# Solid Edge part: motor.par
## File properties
Author: Argu
Template: iso part.par
Last saved by: argo
Revision: 174
Application: Solid Edge
Accuracy: 0,990
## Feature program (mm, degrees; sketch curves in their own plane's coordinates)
lofted protrusion "unnamed LoftedProtrusion 1"
sketch for "unnamed RevolvedProtrusion 1" plane through (0, 0, 0) normal (0.994522, 0, 0.104528) x-axis (0, 1, 0)
  line (24, -36.69) -> (24, -42.69)
revolve "unnamed RevolvedProtrusion 1" add full turn 360 deg
sketch for "väljalase" plane through (0, 213, 0) normal (0, 1, 0) x-axis (-1, 0, 0)
  line (10.5863, -6.6244) -> (4.6567, -16.1368)
  line (-11.713, -4.3174) -> (-7.8564, -14.8423)
extrude "väljalase" add finite 25 along +normal
sketch for "unnamed Protrusion 1" plane through (0, 213, 0) normal (0, 1, 0) x-axis (-1, 0, 0)
  line (10.5863, -6.6244) -> (4.6567, -16.1368)
  line (-11.713, -4.3174) -> (-7.8564, -14.8423)
extrude "unnamed Protrusion 1" add finite 25 along -normal
replace surface "unnamed ReplaceSurface 1"
lofted protrusion "unnamed LoftedProtrusion 2"
sketch for "küljeosapea" plane through (19.2941, 50, 0) normal (0, -1, 0) x-axis (0, 0, -1)
  line (-13.3856, 0.4611) -> (13.3856, 0.4611)
revolve "küljeosapea" add finite 90 deg
sketch for "küljeõhukogur" plane through (22.9602, 97.2349, -43.0717) normal (-0.99115, -0.132749, 2e-06) x-axis (2e-06, 0, 1)
  line (38.5171, 57.7287) -> (15.9515, 59.6618)
  line (15.9515, 59.6618) -> (17.6852, 79.8989)
  line (17.6852, 79.8989) -> (40.2507, 77.9658)
  line (40.2507, 77.9658) -> (38.5171, 57.7287)
extrude "küljeõhukogur" add finite 10 along -normal
sketch for "tiivaühendust90kraadi" plane through (0, 0, 0) normal (1, 0, 0) x-axis (0, 1, 0)
  arc centre (60, 1124.0766) radius 1136.5766 from (60, -12.5) to (165.0001, -7.6395) ccw
  arc centre (60, -384.4611) radius 396.9611 from (60, 12.5) to (165.0006, -1.6387) cw
extrude "tiivaühendust90kraadi" add finite 35 along -normal
lofted protrusion "unnamed LoftedProtrusion 3"
sketch used by "unnamed Cutout 1" plane through (0, 0, 0) normal (0, -1, 0) x-axis (1, 0, 0)
extrude "unnamed Cutout 1" cut finite 25 along -normal
draft "unnamed Draft 1"
sketch used by "küljekogur_tühjaks" plane through (19.4676, 155.9842, -15.8113) normal (0.132264, -0.987533, -0.085355) x-axis (0.99115, 0.132749, -2e-06)
extrude "küljekogur_tühjaks" cut finite 18 along -normal
fillet "unnamed Round 1"
fillet "küljekogurinurgad2" radius 0.5
fillet "küljekogurinurgad3" radius 1
fillet "küljekogurinurgad4" radius 0.5
fillet "küljekogurinurgad5" radius 0.5
web network "väljalaskeava_ribid"  Thickness = 0.25 mm
sketch for "tiivatugi" plane through (0, -24, 0) normal (0, -1, 0) x-axis (1, 0, 0)
  line (-280.7164, 2.3908) -> (-280.5824, 2.3963)
  line (-280.5824, 2.3963) -> (-275.909, -42.0686)
  line (-284.9125, -72.0686) -> (-275.909, -42.0686)
  line (-340.5, -72.0686) -> (-284.9125, -72.0686)
  line (-340.5, -0.0686) -> (-340.5, -72.0686)
  line (-340.5, -0.0686) -> (-340.5, 2.3908)
  line (-280.7164, 2.3908) -> (-340.5, 2.3908)
extrude "tiivatugi" add finite 300 along -normal
fillet "Round_13" radius 25
sketch for "unnamed Cutout 2" plane through (-280.5, 0, 0) normal (1, 0, 0) x-axis (0, 1, 0)
  arc centre (78.2888, -220.2096) radius 222.6118 from (-24, -22.4901) to (79.9131, 2.3963) cw
  line (177.7767, -5.9179) -> (276, -22.4901)
extrude "unnamed Cutout 2" cut to key point along -normal
sketch for "unnamed Cutout 3" plane through (-280.5, 0, 0) normal (1, 0, 0) x-axis (0, 1, 0)
  line (177.7767, -5.9179) -> (276, -22.4901)
extrude "unnamed Cutout 3" cut to key point along +normal
fillet "unnamed Round 2"
sketch for "tiivatugi_tühjaks" plane through (0, -49, 0) normal (0, -1, 0) x-axis (1, 0, 0)
  line (-308.2912, -146.1981) -> (-294.1065, -138.9677)
  line (-294.1065, -138.9677) -> (-293.6547, -137.845)
  arc centre (-385.4277, -100.9117) radius 98.926 from (-293.6547, -137.845) to (-286.5972, -105.2589) ccw
  line (-286.5972, -105.2589) -> (-285.1373, -72.0686)
  line (-285.1373, -72.0686) -> (-289.4197, -42.5492)
  arc centre (-299.6692, -44.0361) radius 10.3568 from (-289.4197, -42.5492) to (-294.2246, -35.2258) ccw
  line (-294.2246, -35.2258) -> (-295.5114, -34.4306)
  arc centre (-311.2831, -59.9517) radius 30.0011 from (-295.5114, -34.4306) to (-309.524, -30.0022) ccw
  line (-309.524, -30.0022) -> (-340.5, -28.1828)
  line (-340.5, -28.1828) -> (-340.5, -148.1828)
  line (-340.5, -148.1828) -> (-308.2912, -146.1981)
extrude "tiivatugi_tühjaks" cut finite 525 along -normal
sketch for "unnamed Protrusion 2" plane through (-310.8984, -24, -43.202) normal (0, -1, 0) x-axis (1, 0, 0)
  line (2.6071, -102.9961) -> (16.7918, -95.7657)
  line (-29.6016, -104.9808) -> (2.6071, -102.9961)
  line (-29.6016, 15.0192) -> (-29.6016, -104.9808)
  line (1.3744, 13.1999) -> (-29.6016, 15.0192)
  arc centre (-0.3847, -16.7496) radius 30.0011 from (15.3869, 8.7714) to (1.3744, 13.1999) ccw
  line (16.6737, 7.9762) -> (15.3869, 8.7714)
  arc centre (11.2291, -0.834) radius 10.3568 from (21.4787, 0.6529) to (16.6737, 7.9762) ccw
  line (25.7611, -28.8666) -> (21.4787, 0.6529)
  line (24.3011, -62.0569) -> (25.7611, -28.8666)
  arc centre (-74.5293, -57.7096) radius 98.926 from (17.2436, -94.643) to (24.3011, -62.0569) ccw
extrude "unnamed Protrusion 2" add to key point along -normal
sketch for "kereninaosa" plane through (-310.8984, -24, -43.202) normal (0, -1, 0) x-axis (1, 0, 0)
  line (2.6071, -102.9961) -> (16.7918, -95.7657)
  line (-29.6016, -104.9808) -> (2.6071, -102.9961)
  line (-29.6016, 15.0192) -> (-29.6016, -104.9808)
  line (1.3744, 13.1999) -> (-29.6016, 15.0192)
  arc centre (-0.3847, -16.7496) radius 30.0011 from (15.3869, 8.7714) to (1.3744, 13.1999) ccw
  line (16.6737, 7.9762) -> (15.3869, 8.7714)
  arc centre (11.2291, -0.834) radius 10.3568 from (21.4787, 0.6529) to (16.6737, 7.9762) ccw
  line (25.7611, -28.8666) -> (21.4787, 0.6529)
  line (24.3011, -62.0569) -> (25.7611, -28.8666)
  arc centre (-74.5293, -57.7096) radius 98.926 from (17.2436, -94.643) to (24.3011, -62.0569) ccw
extrude "kereninaosa" add finite 192 along +normal
lofted protrusion "unnamed LoftedProtrusion 4"
swept protrusion "SweptProtrusion_23"
replace surface "unnamed ReplaceSurface 2"
sketch for "unnamed Cutout 4" plane through (-338.3961, 165.0002, -75) normal (0, 0, 1) x-axis (0, 1, 0)
  arc centre (-334.7471, 13.2391) radius 47.5746 from (-355.6953, -29.4753) to (-381.0002, 2.1039) cw
  line (-340.8749, -38.1444) -> (-355.6953, -29.4753)
  arc centre (-312.4363, 10.4733) radius 56.3243 from (-318.7086, -45.5007) to (-340.8749, -38.1444) cw
  line (-262.505, -51.7988) -> (-318.7086, -45.5007)
  line (-262.505, -51.7988) -> (-223.4421, -53.2588)
extrude "unnamed Cutout 4" cut finite 250 along -normal
sketch for "unnamed Cutout 5" plane through (-338.3961, 165.0002, -75) normal (0, 0, 1) x-axis (0, 1, 0)
  arc centre (-334.7471, 13.2391) radius 47.5746 from (-355.6953, -29.4753) to (-381.0002, 2.1039) cw
  line (-340.8749, -38.1444) -> (-355.6953, -29.4753)
  arc centre (-312.4363, 10.4733) radius 56.3243 from (-318.7086, -45.5007) to (-340.8749, -38.1444) cw
  line (-262.505, -51.7988) -> (-318.7086, -45.5007)
  line (-262.505, -51.7988) -> (-223.4421, -53.2588)
extrude "unnamed Cutout 5" cut to key point along +normal
sketch for "tagatiib" plane through (-340.5, 165.0002, -72.8961) normal (-1, 0, 0) x-axis (0, -1, 0)
  line (-446.2782, 53.6797) -> (-327.0292, 50.3776)
  line (-358.6945, 20.6286) -> (-327.4416, 25.629)
  line (-446.9998, 27.6211) -> (-358.6945, 20.6286)
extrude "tagatiib" add finite 120 along -normal
lofted protrusion "unnamed LoftedProtrusion 5"
lofted protrusion "unnamed LoftedProtrusion 6"
sketch for "unnamed RevolvedProtrusion 2" plane through (-225.6219, 579.9977, 99.9635) normal (0, -0.02768, 0.999617) x-axis (0, 0.999617, 0.02768)
revolve "unnamed RevolvedProtrusion 2" add finite 360 deg
sketch for "unnamed RevolvedProtrusion 3" plane through (-225.6219, 578.047, -80.1595) normal (0, 0.02768, -0.999617) x-axis (1, 0, 0)
  line (0, 44.8751) -> (0, -44.8781)
  arc centre (0, -42.3781) radius 2.5 from (0, -44.8781) to (2.5, -42.3781) ccw
  line (2.5, 42.3751) -> (2.5, -42.3781)
  arc centre (0, 42.3751) radius 2.5 from (2.5, 42.3751) to (0, 44.8751) ccw
revolve "unnamed RevolvedProtrusion 3" add finite 360 deg
body pattern "unnamed BodyPattern 1"
pattern "unnamed Pattern 1"
fillet "Round_41" radius 25
sketch for "kerelaiend" plane through (-340.5, 194.9376, -97.143) normal (-1, 0, 0) x-axis (0, -0.999989, 0.00463)
  line (-161.3545, -6.1088) -> (-30.218, -41.6853)
  line (-30.218, -41.6853) -> (-10.9684, 29.2697)
  line (-5.2997, 50.2919) -> (-10.9684, 29.2697)
  line (-141.7314, 50.9586) -> (-5.2997, 50.2919)
  arc centre (-141.8871, 19.1047) radius 31.8543 from (-141.7314, 50.9586) to (-161.3545, -6.1088) ccw
revolve "kerelaiend" add finite 180 deg
sketch for "kerelaiend2" plane through (0, 224.9622, 0) normal (0, -1, 0) x-axis (1, 0, 0)
  line (-476.3766, -138.9677) -> (-386.8935, -138.9677)
  line (-294.1065, -138.9677) -> (-386.8935, -138.9677)
  line (-204.6234, -138.9677) -> (-294.1065, -138.9677)
  line (-281.8752, -61.9482) -> (-208.6199, -80.7816)
  line (-281.8752, -61.9482) -> (-399.1248, -61.9482)
  line (-399.1248, -61.9482) -> (-472.3801, -80.7816)
extrude "kerelaiend2" add finite 150 along +normal
sketch for "kerelaiend3" plane through (-441.4689, 74.9622, -100.458) normal (0, -1, 0) x-axis (1, 0, 0)
  line (-34.9077, -38.5098) -> (54.5754, -38.5098)
  line (100.9689, -38.5098) -> (54.5754, -38.5098)
  line (100.9689, 38.5098) -> (100.9689, -38.5098)
  line (100.9689, 38.5098) -> (42.3441, 38.5098)
  line (42.3441, 38.5098) -> (-30.9112, 19.6764)
revolve "kerelaiend3" add finite 180 deg
sketch for "rattaava" plane through (-249.3649, 86.1067, -138.9677) normal (0, 0, -1) x-axis (1, 0, 0)
  line (-77.1351, 242.1067) -> (-77.1351, 187.1067)
  line (-77.1351, 187.1067) -> (-108.6108, 187.1067)
  line (-108.6108, 187.1067) -> (-108.6108, 242.1067)
  line (-108.6108, 242.1067) -> (-91.1351, 242.1067)
  line (-91.1351, 242.1067) -> (-77.1351, 242.1067)
extrude "rattaava" cut finite 25 along +normal
sketch for "rattaava2" plane through (-249.3649, 86.1067, -138.9677) normal (0, 0, -1) x-axis (1, 0, 0)
  line (-91.1351, 242.1067) -> (-77.1351, 242.1067)
  line (-77.1351, 242.1067) -> (-77.1351, 187.1067)
  line (-77.1351, 187.1067) -> (-108.6108, 187.1067)
  line (-108.6108, 187.1067) -> (-108.6108, 242.1067)
  line (-108.6108, 242.1067) -> (-91.1351, 242.1067)
extrude "rattaava2" cut finite 5 along -normal
sketch for "tagarattaava" plane through (-249.3649, 86.1067, -138.9677) normal (0, 0, -1) x-axis (1, 0, 0)
  line (12.8649, -36.3933) -> (-18.5846, -36.3933)
  line (-18.5846, -36.3933) -> (-18.5846, -91.3933)
  line (-18.5846, -91.3933) -> (-1.1351, -91.3933)
  line (-1.1351, -91.3933) -> (12.8649, -91.3933)
  line (12.8649, -91.3933) -> (12.8649, -36.3933)
extrude "tagarattaava" cut finite 5 along -normal
mirror "unnamed Mirror 1" of "tagarattaava" about plane through (-340.5, 194.9376, -97.143) normal (-1, 0, 0)
extrude "unnamed Cutout 6" cut finite 5
fillet "unnamed Round 3"
sketch for "kabiiniaken" plane through (-340.5, -157.7277, -58.887) normal (0, -0.783072, 0.621931) x-axis (1, 0, 0)
  arc centre (30.5182, 14.9052) radius 10 from (40.4763, 13.9912) to (34.5082, 24.0747) ccw
  arc centre (0, -55.2287) radius 86.4861 from (34.5082, 24.0747) to (-34.5082, 24.0747) ccw
  arc centre (-30.5182, 14.9052) radius 10 from (-34.5082, 24.0747) to (-40.4763, 13.9912) ccw
  line (-40.4763, 13.9912) -> (-37.917, -13.8913)
  arc centre (-32.9379, -13.4343) radius 5 from (-32.9379, -18.4343) to (-37.917, -13.8913) cw
  line (32.9379, -18.4343) -> (-32.9379, -18.4343)
  arc centre (32.9379, -13.4343) radius 5 from (32.9379, -18.4343) to (37.917, -13.8913) ccw
  line (37.917, -13.8913) -> (40.4763, 13.9912)
extrude "kabiiniaken" cut finite 100 along -normal
sketch for "unnamed Cutout 7" plane through (0, -138.2878, 0) normal (0, -1, 0) x-axis (1, 0, 0)
  line (-380.9763, -47.9309) -> (-378.417, -69.7649)
  line (-378.417, -69.7649) -> (-372.0792, -117.1998)
  line (-308.9208, -116.8926) -> (-372.0792, -117.1998)
  line (-302.583, -69.7649) -> (-308.9208, -116.8926)
  line (-302.583, -69.7649) -> (-300.0237, -47.9309)
extrude "unnamed Cutout 7" cut to key point along -normal
thinwall "Thinwall_22"  Thickness = 0.01 mm
cool vent "õhuaugud"  RibDepth = 2 mm; SparThickness = 2 mm; SparDepth = 2 mm
sketch for "tankimistoru" plane through (0, 0, 0) normal (0, -1, 0) x-axis (1, 0, 0)
  circle centre (-373.4379, -131.7498) radius 7.5
extrude "tankimistoru" add finite 225 along +normal
lofted protrusion "unnamed LoftedProtrusion 7"
fillet "unnamed Round 4"
sketch for "unnamed Protrusion 3" plane through (-272.2835, -18.9938, -29.5985) normal (-0.956613, -0.001235, -0.291359) x-axis (0.00068, 0.999979, -0.006472)
  circle centre (35.1937, 14.8267) radius 17.5
extrude "unnamed Protrusion 3" add to key point along +normal
sketch for "unnamed Protrusion 4" plane through (-272.2835, -18.9938, -29.5985) normal (-0.956613, -0.001235, -0.291359) x-axis (0.00068, 0.999979, -0.006472)
  circle centre (79.539, 14.5434) radius 17.5
extrude "unnamed Protrusion 4" add to key point along +normal
sketch for "unnamed Cutout 8" #1 plane through (-277.0665, -19, -31.0553) normal (-0.956613, -0.001235, -0.291359) x-axis (0.00068, 0.999979, -0.006472)
  circle centre (80.122, 14.5396) radius 14.5443
sketch for "unnamed Cutout 8" #2 plane through (-277.0665, -19, -31.0553) normal (-0.956613, -0.001235, -0.291359) x-axis (0.00068, 0.999979, -0.006472)
  circle centre (35.1937, 14.8267) radius 14.5443
extrude "unnamed Cutout 8" cut to key point symmetric
sketch for "ExtrudedCutout_50" #1 plane through (-413.0604, 16.1044, -44.0095) normal (-0.956613, 0.001235, 0.291359) x-axis (0, -0.999991, 0.004239)
sketch for "ExtrudedCutout_50" #2 plane through (-413.0604, 16.1044, -44.0095) normal (-0.956613, 0.001235, 0.291359) x-axis (0, -0.999991, 0.004239)
  circle centre (0, 0) radius 12.5
extrude "ExtrudedCutout_50" cut finite 100 symmetric
swept protrusion "v_5"
swept protrusion "SweptProtrusion_31"
sketch for "ExtrudedCutout_53" plane through (0, -172.7051, 0) normal (0, -1, 0) x-axis (1, 0, 0)
  circle centre (-324.4536, -98.0234) radius 1.5
extrude "ExtrudedCutout_53" cut finite 50 along -normal
sketch used by "unnamed Protrusion 5" plane through (0, 0, -124.2498) normal (0, 0, 1) x-axis (1, 0, 0)
  circle centre (-326.49, -90.8853) radius 15.8853
extrude "unnamed Protrusion 5" add to key point along -normal
sketch for "unnamed Protrusion 6" plane through (0, 0, -124.2498) normal (0, 0, 1) x-axis (1, 0, 0)
extrude "unnamed Protrusion 6" add to key point along +normal
mirror "unnamed Mirror 2" of "unnamed Protrusion 6" about plane through (-340.5, 194.9376, -97.143) normal (-1, 0, 0)
extrude "unnamed Protrusion 7" add finite 7.1937
sketch for "unnamed Protrusion 8" plane through (-340.4999, -156.6378, -57.5146) normal (0, 0.783072, -0.621931) x-axis (1, -2e-06, -2e-06)
extrude "unnamed Protrusion 8" add finite 5 symmetric
mirror "unnamed Mirror 3" of "unnamed Protrusion 8" about plane through (-340.5, 194.9376, -97.143) normal (-1, 0, 0)
extrude "unnamed Protrusion 9" add finite 5 symmetric
thicken "Thicken_12"  Distance1 = 10 mm
thicken "Thicken_14"  Distance1 = 3.175 mm
thicken "Thicken_15"  Distance1 = 3.175 mm
thicken "Thicken_16"  Distance1 = 3.175 mm
sketch for "ExtrudedProtrusion_60" plane through (-340.5, -157.7277, -58.887) normal (0, -0.783072, 0.621931) x-axis (1, 0, 0)
extrude "ExtrudedProtrusion_60" add finite 1 symmetric
mirror "unnamed Mirror 4" of "unnamed Protrusion 3", "unnamed Protrusion 4" about plane through (-340.5, 194.9376, -97.143) normal (-1, 0, 0)
extrude "unnamed Protrusion 10" add finite 7.5912
extrude "unnamed Protrusion 11" add finite 9.8234
mirror "unnamed Mirror 5" of "unnamed Cutout 8" about plane through (-340.5, 194.9376, -97.143) normal (-1, 0, 0)
extrude "unnamed Cutout 9" cut finite 71.1226 symmetric
sketch for "unnamed Protrusion 12" #1 plane through (-267.9396, 16.1044, -44.0095) normal (0.956613, 0.001235, 0.291359) x-axis (0.291359, 0, -0.956614)
  circle centre (0, 0) radius 14.5443
sketch for "unnamed Protrusion 12" #2 plane through (-267.9396, 16.1044, -44.0095) normal (0.956613, 0.001235, 0.291359) x-axis (0.291359, 0, -0.956614)
  circle centre (0, 44.9293) radius 14.5443
extrude "unnamed Protrusion 12" add finite 5 along -normal
sketch for "ExtrudedCutout_57" #1 plane through (-267.9396, 16.1044, -44.0095) normal (0.956613, 0.001235, 0.291359) x-axis (0.291359, 0, -0.956614)
  circle centre (0, 0) radius 14.5443
sketch for "ExtrudedCutout_57" #2 plane through (-267.9396, 16.1044, -44.0095) normal (0.956613, 0.001235, 0.291359) x-axis (0.291359, 0, -0.956614)
extrude "ExtrudedCutout_57" cut finite 4 along -normal
sketch for "unnamed Protrusion 13" #1 plane through (-413.008, 60.4506, -44.0254) normal (-0.956613, 0.001235, 0.291359) x-axis (0, -0.999991, 0.004239)
  circle centre (-0.5831, 0.0024) radius 14.5443
sketch for "unnamed Protrusion 13" #2 plane through (-413.008, 60.4506, -44.0254) normal (-0.956613, 0.001235, 0.291359) x-axis (0, -0.999991, 0.004239)
  circle centre (44.3458, -0.1798) radius 14.5443
extrude "unnamed Protrusion 13" add to key point along -normal
sketch for "unnamed Cutout 10" #1 plane through (-413.008, 60.4506, -44.0254) normal (-0.956613, 0.001235, 0.291359) x-axis (0, -0.999991, 0.004239)
  circle centre (-0.5831, 0.0024) radius 14.5443
sketch for "unnamed Cutout 10" #2 plane through (-413.008, 60.4506, -44.0254) normal (-0.956613, 0.001235, 0.291359) x-axis (0, -0.999991, 0.004239)
  circle centre (44.3458, -0.1798) radius 14.5443
extrude "unnamed Cutout 10" cut finite 4 along -normal
Other named dimensions: "ExtrudedSurface_3": FiniteDepth = 50 mm | "ExtrudedSurface_14": FiniteDepth = 150 mm | "ExtrudedSurface_20": FiniteDepth = 275 mm
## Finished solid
Body 1: solid body, 4 faces, 10 edges, 8 vertices.
  Faces by surface: plane 2, spline 2
  Edges by curve: line 6, circle 2, spline 2
Body 2: solid body, 4 faces, 10 edges, 8 vertices.
  Faces by surface: plane 2, spline 2
  Edges by curve: line 6, circle 2, spline 2
Body 3: sheet body, 1 face, 1 edge, 0 vertices.
  Faces by surface: plane 1
  Edges by curve: circle 1
Body 4: sheet body, 1 face, 1 edge, 0 vertices.
  Faces by surface: plane 1
  Edges by curve: circle 1
Body 5: sheet body, 1 face, 12 edges, 12 vertices.
  Faces by surface: plane 1
  Edges by curve: circle 5, line 5, spline 2
Body 6: sheet body, 1 face, 4 edges, 4 vertices.
  Faces by surface: plane 1
  Edges by curve: line 4
Body 7: sheet body, 1 face, 8 edges, 8 vertices.
  Faces by surface: spline 1
  Edges by curve: intersection 4, circle 2, spline 2
Body 8: solid body, 3 faces, 2 edges, 0 vertices.
  Faces by surface: plane 2, spline 1
  Edges by curve: circle 2
Body 9: sheet body, 5 faces, 16 edges, 12 vertices.
  Faces by surface: plane 3, cylinder 2
  Edges by curve: line 12, circle 4
Body 10: sheet body, 15 faces, 46 edges, 32 vertices.
  Faces by surface: plane 8, cylinder 7
  Edges by curve: line 32, circle 14
Body 11: sheet body, 1 face, 4 edges, 4 vertices.
  Faces by surface: cylinder 1
  Edges by curve: circle 2, line 2
Body 12: solid body, 3 faces, 2 edges, 0 vertices.
  Faces by surface: plane 2, spline 1
  Edges by curve: circle 2
Body 13: sheet body, 1 face, 8 edges, 8 vertices.
  Faces by surface: spline 1
  Edges by curve: intersection 4, circle 2, spline 2
Body 14: sheet body, 1 face, 4 edges, 4 vertices.
  Faces by surface: spline 1
  Edges by curve: circle 2, spline 2
Body 15: solid body, 1466 faces, 4095 edges, 2656 vertices, 10 internal voids.
  Faces by surface: plane 700, cylinder 388, spline 134, offset 117, torus 49, sphere 28, blend 20, cone 17, swept 11, spun 2
  Edges by curve: line 1791, intersection 1063, circle 683, curve on surface 264, ellipse 215, spline 79
Bounding box of the edges (mm; curved faces can reach further): 746.375 x 910.039 x 348.642, from (-713.6876, -285, -246.1983) to (32.6876, 625.0393, 102.4439).
Cylindrical faces by radius (mm): R0.49 x14, R0.5 x20, R0.51 x6, R1 x4, R1.01 x4, R1.49 x2, R1.5 x3, R1.99 x10, R2 x10, R2.49 x2, R2.5 x2, R2.9904 x2, R3.0004 x2, R3.9281 x8, R3.9381 x8, R4.1681 x8, R4.1781 x8, R4.99 x3, R5 x9, R5.01 x4, R6.932 x8, R6.942 x8, R6.99 x5, R7 x5, R7.172 x8, R7.182 x8, R7.1982 x1, R7.2082 x2, R7.5 x3, R8.3568 x5, R9.4747 x8, R9.4847 x8, R9.7147 x2, R9.7247 x2, R10 x8, R10.01 x4, R10.3468 x2, R10.3568 x2, R11.8334 x12, R12.3677 x2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
Conical faces (half-angle, radius in mm at the cone's reference point): 2.6612 deg R5.2789 x4, 2.6612 deg R5.2888 x4, 3.7063 deg R3.6133 x1, 75.1013 deg R0.0308 x2, 75.1013 deg R0.0334 x2, 75.5819 deg R58.6223 x2, 75.5819 deg R58.6248 x2
Toroidal faces (ring radius, tube radius in mm): R-0.4611 r13.3835 x2, R-0.4611 r13.3935 x2, R0.5 r0.5 x4, R0.5 r0.51 x4, R1.5 r0.49 x8, R1.5 r0.5 x8, R1.7387 r2 x1, R14.5071 r2.99 x6, R14.5071 r3 x6, R20 r4.99 x2, R20 r5 x2, R123.69 r31.8443 x2, R123.69 r31.8543 x2
Spherical faces by radius (mm): R1.49 x4, R1.5 x4, R1.99 x4, R2 x4, R2.49 x4, R2.5 x4, R4.99 x2, R5 x2
Planar faces by outward normal: +x 15, +y 100, +z 10, -x 15, -y 97, -z 14, oblique 457
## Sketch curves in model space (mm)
circle centre (-413.0604, 16.1044, -44.0095) radius 14.5443
circle centre (-413.0073, 61.0336, -44.0256) radius 14.5443
circle centre (-267.9927, 61.0336, -44.0256) radius 14.5443
circle centre (-267.9396, 16.1044, -44.0095) radius 14.5443
circle centre (-324.4536, -172.7051, -98.0234) radius 1.5
circle centre (-326.49, -90.8853, -124.2498) radius 15.8853
circle centre (-354.2265, 263.942, -20.4557) radius 1.45
circle centre (-326.7724, 263.942, -20.4557) radius 1.4495
circle centre (-413.008, 60.4506, -44.0254) radius 12.5
circle centre (-413.0604, 16.1044, -44.0095) radius 12.5
circle centre (-340.4995, 243.1605, -16.9494) radius 25.1515
line (-340.4994, 263.942, -20.4557) -> (-340.4995, 220.3143, -13.0948)
line (-371.1216, 244.4877, -17.1733) -> (-307.7088, 244.4877, -17.1733)
arc centre (-340.5, 239.3803, -33.0617) radius 27.6078 from (-340.5, 263.942, -20.4557) through (-340.5, 243.1552, -5.7132) to (-340.5, 220.3143, -13.0948)
circle centre (-267.992, 60.4506, -44.0254) radius 17.5
circle centre (-267.9396, 16.1044, -44.0095) radius 17.5
circle centre (-272.7758, 61.0274, -45.4824) radius 14.5443
circle centre (-272.7227, 16.0982, -45.4663) radius 14.5443
circle centre (-373.4379, -285, -131.7498) radius 3.6133
circle centre (-373.4379, 0, -131.7498) radius 7.5
line (-286.1296, -83.9663, -65.2284) -> (-289.3445, -83.9663, -43.0672)
line (-288.8681, -78.9663, -46.3511) -> (-286.606, -78.9663, -61.9446)
line (-285.9348, -93.5164, -66.5712) -> (-289.5393, -93.5164, -41.7245)
line (-289.4584, -88.5164, -42.2824) -> (-286.0158, -88.5164, -66.0132)
line (-285.8452, -103.1116, -67.1886) -> (-289.6289, -103.1116, -41.107)
line (-289.6137, -98.1116, -41.2117) -> (-285.8604, -98.1116, -67.084)
line (-286.0487, -107.3914, -65.786) -> (-289.4254, -107.3914, -42.5097)
line (-288.7584, -112.3914, -47.1076) -> (-286.7157, -112.3914, -61.1881)
line (-288.8733, -111.8447, -46.3159) -> (-288.8733, -78.9982, -46.3159)
line (-288.1581, -76.3317, -51.2454) -> (-288.1727, -114.099, -51.1453)
line (-287.4561, -114.3045, -56.0848) -> (-287.4561, -76.1254, -56.0848)
line (-286.7382, -78.2237, -61.033) -> (-286.7382, -112.4888, -61.033)
line (-286.1024, -108.0472, -65.4161) -> (-286.1024, -84.5736, -65.4161)
line (-289.5911, -98.1116, -41.3677) -> (-289.5911, -96.7139, -41.3677)
arc centre (-287.7371, -87.7958, -54.1478) radius 11.8334 from (-289.4253, -86.4699, -42.5108) through (-287.636, -75.9834, -54.8446) to (-286.0489, -86.4699, -65.7849)
line (-285.8359, -99.6292, -67.2533) -> (-286.0489, -86.4699, -65.7849)
arc centre (-287.7371, -101.1224, -54.1478) radius 13.3266 from (-285.8359, -99.6292, -67.2533) through (-287.7371, -114.449, -54.1478) to (-289.6383, -99.6292, -41.0424)
line (-289.6383, -99.6292, -41.0424) -> (-289.4253, -86.4699, -42.5108)
arc centre (-340.4833, -177.1142, -83.2964) radius 69.3237 from (-340.5013, -133.9997, -29.011) through (-351.8665, -134.5849, -29.7479) to (-362.9238, -136.321, -31.9338)
line (-340.5, -137.1093, -32.9263) -> (-340.5013, -133.9997, -29.011)
spline (-361.2197, -139.2472, -35.6182) -> (-350.9878, -137.6789, -33.6435) -> (-340.5, -137.1093, -32.9263)
line (-375.0122, -142.7492, -40.0275) -> (-361.2197, -139.2472, -35.6182)
arc centre (-371.0182, -148.4577, -47.2151) radius 10.01 from (-375.0122, -142.7492, -40.0275) through (-377.2485, -143.585, -41.08) to (-379.0616, -144.7519, -42.5492)
arc centre (-371.0182, -148.4577, -47.2151) radius 10.01 from (-379.0616, -144.7519, -42.5492) through (-380.6579, -146.7801, -45.1028) to (-380.9859, -149.0289, -47.9344)
line (-380.9859, -149.0289, -47.9344) -> (-378.4168, -166.3682, -69.7662)
arc centre (-373.4379, -166.0829, -69.407) radius 5 from (-378.4168, -166.3682, -69.7662) through (-376.6966, -168.4414, -72.3766) to (-373.4379, -169.1926, -73.3223)
line (-373.4379, -169.1926, -73.3223) -> (-340.5, -169.1926, -73.3223)
line (-340.5, -169.1926, -73.3223) -> (-340.5, -172.3022, -77.2377)
line (-340.5, -172.3022, -77.2377) -> (-373.4379, -172.3022, -77.2377)
line (-376.9495, -139.8823, -36.4178) -> (-363.1096, -136.3682, -31.9933)
arc centre (-371.0182, -148.4577, -47.2151) radius 15.01 from (-376.9495, -139.8823, -36.4178) through (-380.336, -141.139, -38.0002) to (-383.0793, -142.9009, -40.2186)
arc centre (-371.0182, -148.4577, -47.2151) radius 15.01 from (-383.0793, -142.9009, -40.2186) through (-385.4723, -145.9408, -44.0461) to (-385.9653, -149.3116, -48.2902)
line (-385.9653, -149.3116, -48.2902) -> (-383.396, -166.652, -70.1236)
arc centre (-373.4379, -166.0829, -69.407) radius 10 from (-383.396, -166.652, -70.1236) through (-379.9562, -170.7994, -75.3455) to (-373.4379, -172.3022, -77.2377)
line (-340.4998, -137.1093, -32.9263) -> (-340.5, -176.1663, -82.1029)
line (-340.4998, -136.5414, -32.2113) -> (-340.5, -170.6579, -75.1673)
line (-319.7803, -139.2472, -35.6182) -> (-307.8887, -142.2582, -39.4093)
arc centre (-310.371, -148.5256, -47.3005) radius 10.3785 from (-307.8887, -142.2582, -39.4093) through (-301.9593, -144.7446, -42.54) to (-300.0237, -149.0262, -47.9309)
line (-302.583, -166.3671, -69.7649) -> (-300.0237, -149.0262, -47.9309)
arc centre (-307.5621, -166.0829, -69.407) radius 5 from (-307.5621, -169.1926, -73.3223) through (-304.0842, -168.3171, -72.22) to (-302.583, -166.3671, -69.7649)
line (-373.4379, -169.1926, -73.3223) -> (-307.5621, -169.1926, -73.3223)
arc centre (-373.4379, -166.0829, -69.407) radius 5 from (-378.417, -166.3671, -69.7649) through (-376.6973, -168.4411, -72.3761) to (-373.4379, -169.1926, -73.3223)
line (-380.9863, -149.0267, -47.9316) -> (-378.417, -166.3671, -69.7649)
arc centre (-371.0182, -148.4577, -47.2151) radius 10.01 from (-379.0616, -144.7519, -42.5492) through (-380.6574, -146.779, -45.1015) to (-380.9863, -149.0267, -47.9316)
arc centre (-371.0182, -148.4577, -47.2151) radius 10.01 from (-375.0122, -142.7492, -40.0275) through (-377.2485, -143.585, -41.08) to (-379.0616, -144.7519, -42.5492)
line (-375.0122, -142.7492, -40.0275) -> (-361.2197, -139.2472, -35.6182)
spline (-361.2197, -139.2472, -35.6182) -> (-340.5832, -137.1093, -32.9264) -> (-319.7803, -139.2472, -35.6182)
ellipse centre (-340.5, -138.2878, -102.135) radii 86.4861, 67.7249 from (-305.9918, -138.2878, -40.0347) through (-340.5, -138.2878, -34.4101) to (-375.0082, -138.2878, -40.0347)
ellipse centre (-371.0182, -138.2878, -47.2151) radii 10, 7.8307 from (-375.0082, -138.2878, -40.0347) through (-379.7718, -138.2878, -43.4292) to (-380.9763, -138.2878, -47.9309)
line (-380.9763, -138.2878, -47.9309) -> (-378.417, -138.2878, -69.7649)
line (-378.417, -138.2878, -69.7649) -> (-372.0792, -138.2878, -117.1998)
line (-308.9208, -138.2878, -116.8926) -> (-372.0792, -138.2878, -117.1998)
line (-302.583, -138.2878, -69.7649) -> (-308.9208, -138.2878, -116.8926)
line (-302.583, -138.2878, -69.7649) -> (-300.0237, -138.2878, -47.9309)
ellipse centre (-309.9818, -138.2878, -47.2151) radii 10, 7.8307 from (-300.0237, -138.2878, -47.9309) through (-301.5318, -138.2878, -43.0275) to (-305.9918, -138.2878, -40.0347)
arc centre (-373.4379, -166.0829, -69.407) radius 5 from (-373.4379, -169.1926, -73.3223) through (-376.9158, -168.3171, -72.22) to (-378.417, -166.3671, -69.7649)
line (-380.9763, -149.0262, -47.9309) -> (-378.417, -166.3671, -69.7649)
arc centre (-371.0182, -148.4577, -47.2151) radius 10 from (-375.0082, -142.7549, -40.0347) through (-379.7718, -145.4509, -43.4292) to (-380.9763, -149.0262, -47.9309)
arc centre (-340.5, -192.0762, -102.135) radius 86.4861 from (-305.9918, -142.7549, -40.0347) through (-340.5, -138.2878, -34.4101) to (-375.0082, -142.7549, -40.0347)
arc centre (-309.9818, -148.4577, -47.2151) radius 10 from (-300.0237, -149.0262, -47.9309) through (-301.5318, -145.1318, -43.0275) to (-305.9918, -142.7549, -40.0347)
line (-302.583, -166.3671, -69.7649) -> (-300.0237, -149.0262, -47.9309)
arc centre (-307.5621, -166.0829, -69.407) radius 5 from (-307.5621, -169.1926, -73.3223) through (-304.0842, -168.3171, -72.22) to (-302.583, -166.3671, -69.7649)
line (-307.5621, -169.1926, -73.3223) -> (-373.4379, -169.1926, -73.3223)
line (-340.5, -135.3268, -34.4306) -> (-340.5, -213.8888, -100.1346)
line (-326.5, -156, -138.9677) -> (-326.5, -101, -138.9677)
line (-326.5, -101, -138.9677) -> (-357.9757, -101, -138.9677)
line (-357.9757, -101, -138.9677) -> (-357.9757, -156, -138.9677)
line (-357.9757, -156, -138.9677) -> (-340.5, -156, -138.9677)
line (-340.5, -156, -138.9677) -> (-326.5, -156, -138.9677)
line (-236.5, 177.5, -138.9677) -> (-236.5, 122.5, -138.9677)
line (-236.5, 122.5, -138.9677) -> (-267.9495, 122.5, -138.9677)
line (-267.9495, 122.5, -138.9677) -> (-267.9495, 177.5, -138.9677)
line (-267.9495, 177.5, -138.9677) -> (-250.5, 177.5, -138.9677)
line (-250.5, 177.5, -138.9677) -> (-236.5, 177.5, -138.9677)
line (-340.5, 74.9622, -138.9677) -> (-386.8935, 74.9622, -138.9677)
line (-476.3766, 74.9622, -138.9677) -> (-386.8935, 74.9622, -138.9677)
ellipse centre (-464.19, 74.9622, -110.5281) radii 31.8543, 30.7813 from (-472.3801, 74.9622, -80.7816) through (-495.9744, 74.9622, -108.4895) to (-476.3766, 74.9622, -138.9677)
line (-399.1248, 74.9622, -61.9482) -> (-472.3801, 74.9622, -80.7816)
line (-340.5, 74.9622, -61.9482) -> (-399.1248, 74.9622, -61.9482)
line (-340.5, 74.9622, -61.9482) -> (-340.5, 74.9622, -138.9677)
ellipse centre (-216.81, 224.9622, -110.5281) radii 31.8543, 30.7813 from (-208.6199, 224.9622, -80.7816) through (-185.0256, 224.9622, -108.4895) to (-204.6234, 224.9622, -138.9677)
line (-204.6234, 224.9622, -138.9677) -> (-294.1065, 224.9622, -138.9677)
line (-294.1065, 224.9622, -138.9677) -> (-386.8935, 224.9622, -138.9677)
line (-476.3766, 224.9622, -138.9677) -> (-386.8935, 224.9622, -138.9677)
ellipse centre (-464.19, 224.9622, -110.5281) radii 31.8543, 30.7813 from (-472.3801, 224.9622, -80.7816) through (-495.9744, 224.9622, -108.4895) to (-476.3766, 224.9622, -138.9677)
line (-399.1248, 224.9622, -61.9482) -> (-472.3801, 224.9622, -80.7816)
line (-281.8752, 224.9622, -61.9482) -> (-399.1248, 224.9622, -61.9482)
line (-281.8752, 224.9622, -61.9482) -> (-208.6199, 224.9622, -80.7816)
line (-340.5, 224.9622, -138.9677) -> (-340.5, 206.0413, -67.9244)
line (-340.5, 200.4701, -46.8762) -> (-340.5, 206.0413, -67.9244)
line (-340.5, 336.9034, -46.8412) -> (-340.5, 200.4701, -46.8762)
arc centre (-340.5, 336.9116, -78.6955) radius 31.8543 from (-340.5, 336.9034, -46.8412) through (-340.5, 367.0824, -68.477) to (-340.5, 356.262, -103.9988)
line (-340.5, 356.262, -103.9988) -> (-340.5, 224.9622, -138.9677)
arc centre (-225.6219, 615.4264, 100.9445) radius 1.5 from (-227.1219, 615.4264, 100.9445) through (-225.5775, 616.9252, 100.986) to (-224.1219, 615.4264, 100.9445)
line (-224.1219, 544.5691, 98.9824) -> (-224.1219, 615.4264, 100.9445)
arc centre (-225.6219, 544.5691, 98.9824) radius 1.5 from (-224.1219, 544.5691, 98.9824) through (-225.6664, 543.0703, 98.9409) to (-227.1219, 544.5691, 98.9824)
line (-227.1219, 544.5691, 98.9824) -> (-227.1219, 615.4264, 100.9445)
line (-224.1219, 615.4264, 100.9445) -> (-224.1219, 544.5691, 98.9824)
arc centre (-225.6219, 615.4264, 100.9445) radius 1.5 from (-225.6219, 616.9259, 100.986) through (-224.5309, 616.4554, 100.973) to (-224.1219, 615.4264, 100.9445)
line (-225.6219, 543.0697, 98.9409) -> (-225.6219, 616.9259, 100.986)
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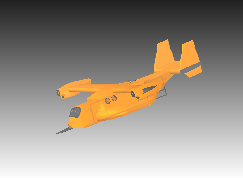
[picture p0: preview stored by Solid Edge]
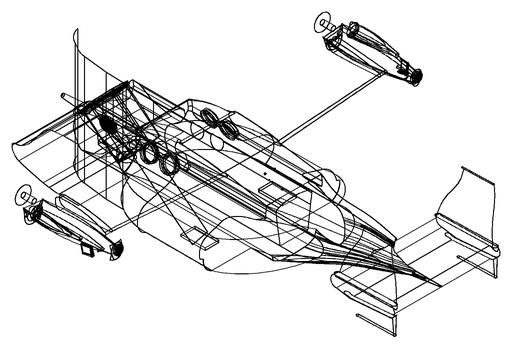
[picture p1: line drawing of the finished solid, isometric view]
